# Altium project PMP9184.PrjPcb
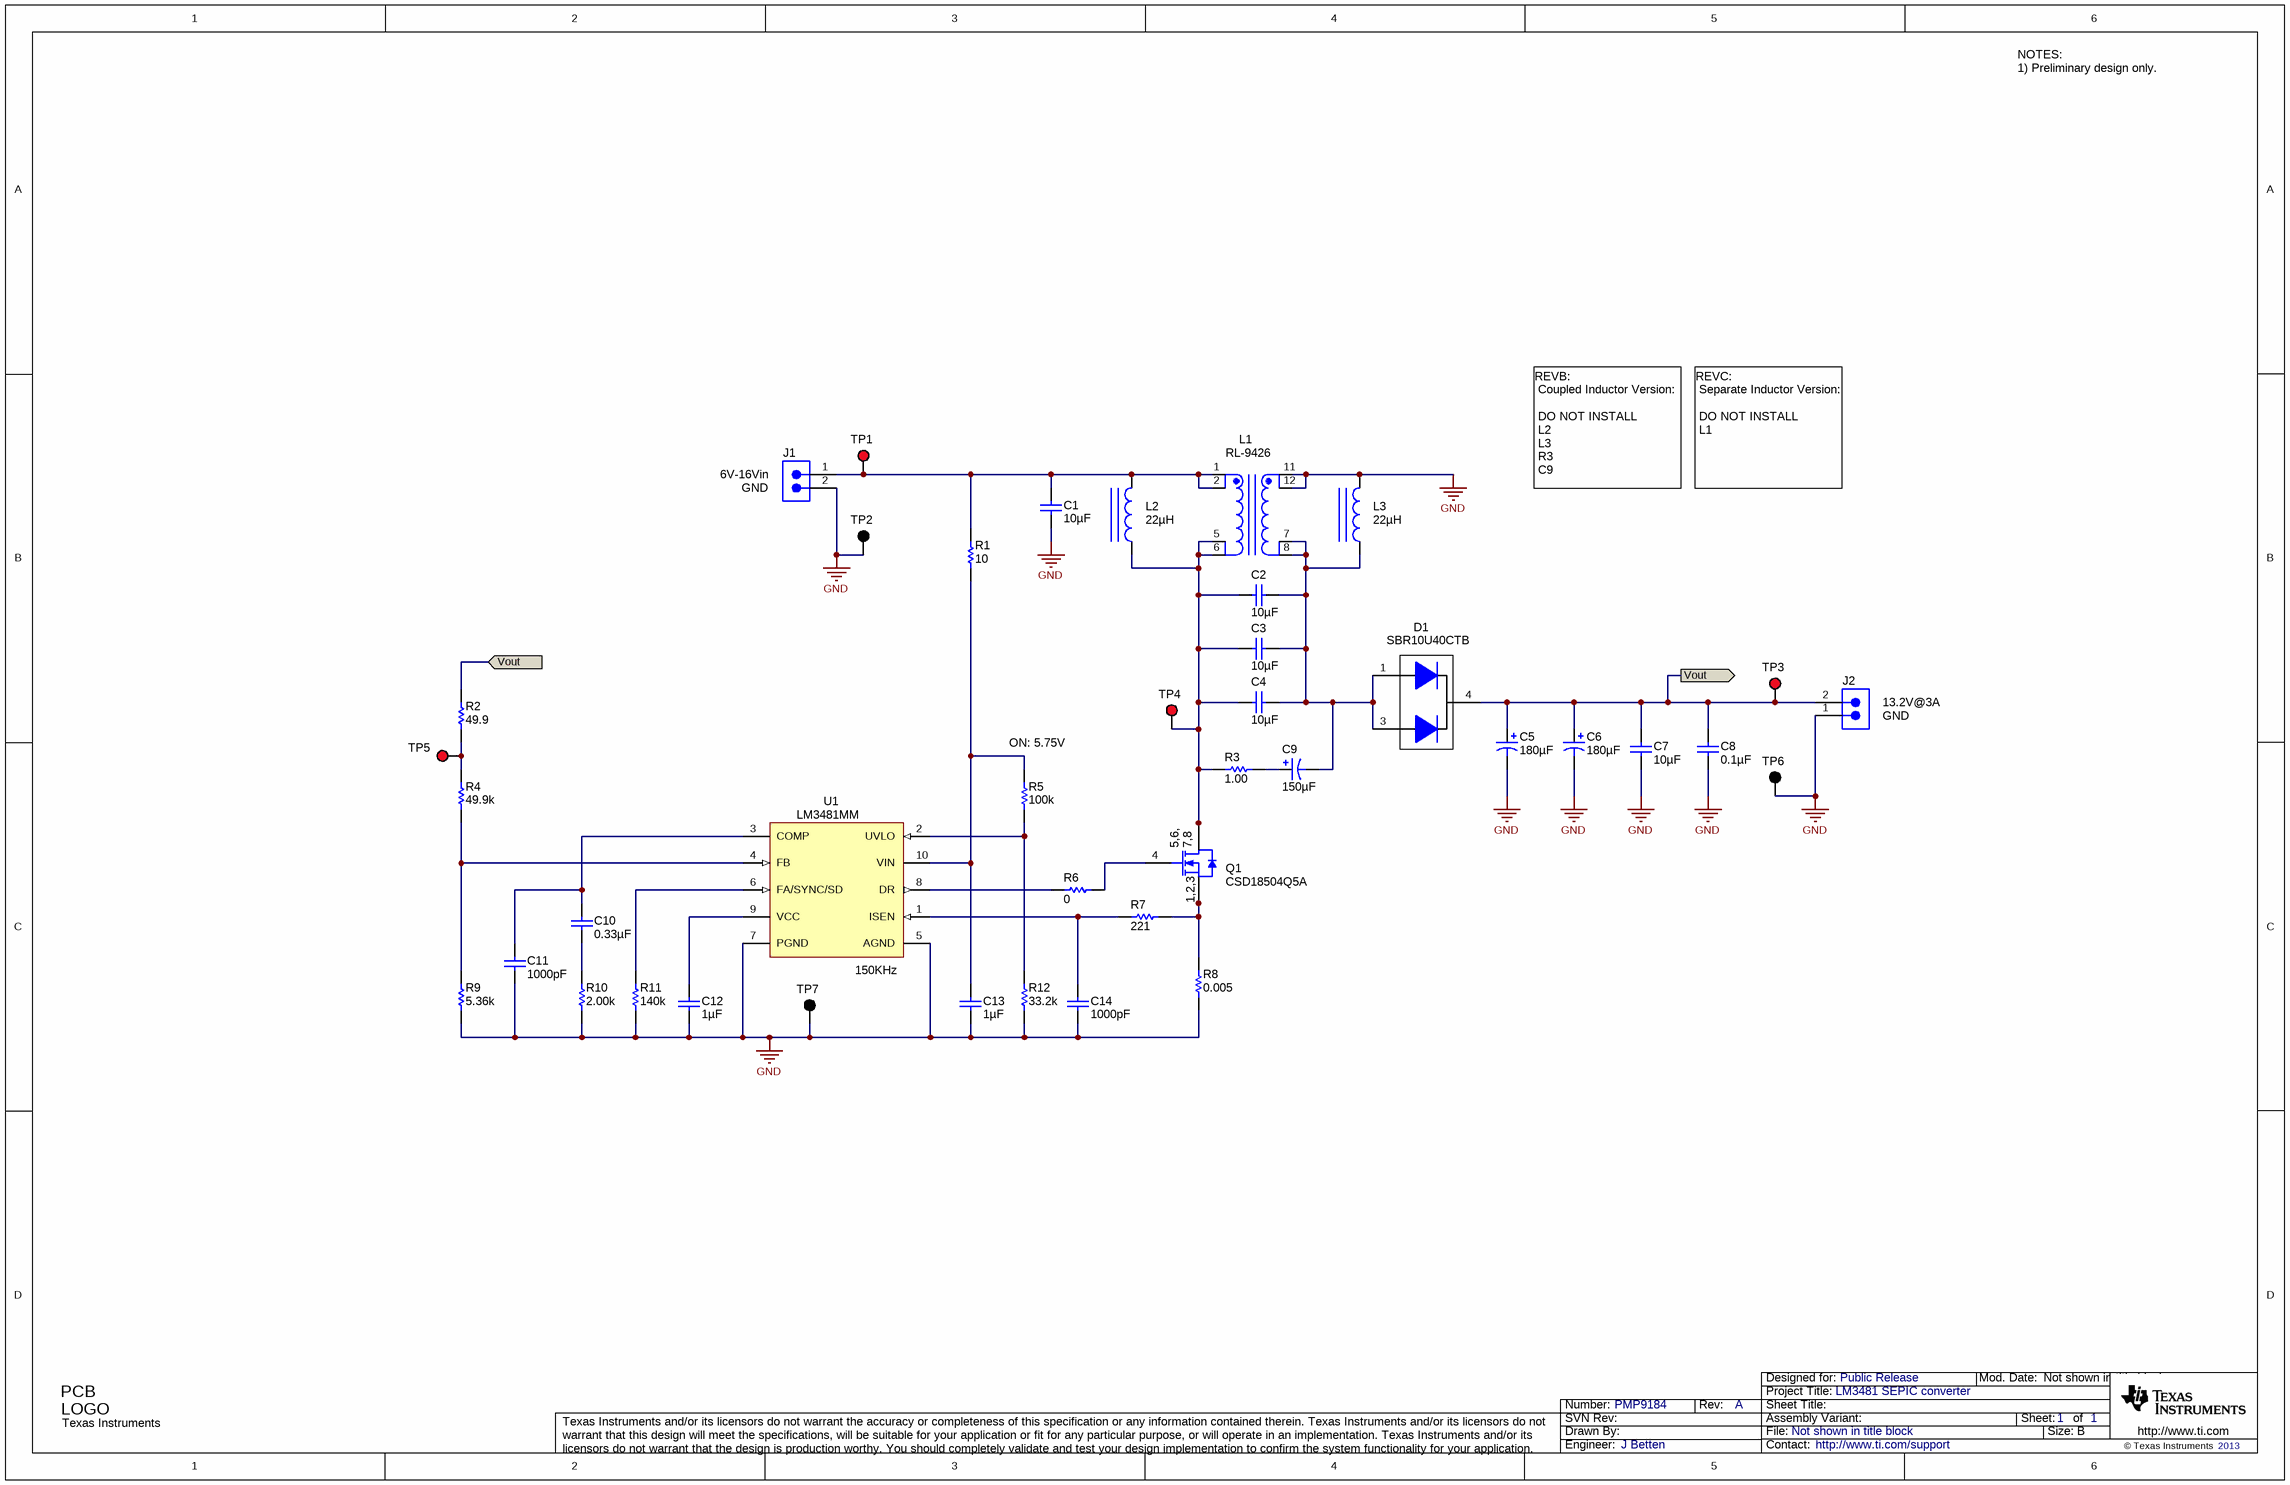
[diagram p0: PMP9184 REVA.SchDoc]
TechSupport: http://www.ti.com/support; SCH_Rev: A; PRJ_Title: LM3481 SEPIC converter; PRJ_Number: PMP9184; PRJ_Engineer: J Betten; PRJ_Customer: Public Release; PCB_Rev: A; PCB_Layout: J Betten; CopyrightYear: 2013
1 sheet, 42 parts. Net scope: flat (ports and power ports of the same name join across sheets).
Board file: PMP9184 REVA.PcbDoc

## Sheet PMP9184 REVA.SchDoc
size 431 x 279 mm; Date: Not shown in title block; ApprovedBy: Not shown in title block; CheckedBy: Not shown in title block; Author: Not shown in title block; CompanyName: Not shown in title block; Engineer: Not shown in title block; Organization: Not shown in title block; Address1: Not shown in title block; Address2: Not shown in title block; Address3: Not shown in title block; Address4: Not shown in title block; DocumentNumber: 1; Revision: Use project parameter SCH_Rev; SheetNumber: 1; SheetTotal: 1; PageSetup: Record=PageOptions|CenterHorizontal=True|CenterVertical=True|PrintScale=1.00|XCorrection=1.00|YCorrection=1.00|PrintKind=0|BorderSize=5000000|LeftOffset=0|BottomOffset=0|Orientation=2|PaperLength=1000|PaperWidth=1000|Scale=100|PaperSource=15|PrintQuality=600|MediaType=1|DitherType=10|PaperKind=Letter|PrintScaleMode=1

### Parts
C1  ValueDisplayed: 10µF  [1210L]  (hidden comment: C3225X7R1E106M250AC)
C2  ValueDisplayed: 10µF  [1210L]  (hidden comment: C3225X7R1E106M250AC)
C3  ValueDisplayed: 10µF  [1210L]  (hidden comment: C3225X7R1E106M250AC)
C4  ValueDisplayed: 10µF  [1210L]  (hidden comment: C3225X7R1E106M250AC)
C5  ValueDisplayed: 180µF  [SM_RADIAL_10AMM]  (hidden comment: 25SVPF180M)
C6  ValueDisplayed: 180µF  [SM_RADIAL_10AMM]  (hidden comment: 25SVPF180M)
C7  ValueDisplayed: 10µF  [1210L]  (hidden comment: C3225X7R1E106M250AC)
C8  ValueDisplayed: 0.1µF  [0603L]  (hidden comment: C1608X7R1H104K)
C9  ValueDisplayed: 150µF  [SM_RADIAL_F]  (hidden comment: EEE-FK1E151P)
C10  ValueDisplayed: 0.33µF  [0603L]  (hidden comment: C1608X5R1E474K)
C11  ValueDisplayed: 1000pF  [0603L]  (hidden comment: C1608X7R1H102K)
C12  ValueDisplayed: 1µF  [0603L]  (hidden comment: C1608X7R1E105K)
C13  ValueDisplayed: 1µF  [0603L]  (hidden comment: C1608X7R1E105K)
C14  ValueDisplayed: 1000pF  [0603L]  (hidden comment: C1608X7R1H102K)
D1  SBR10U40CTB  [DDPAK]
J1  ED555/2DS  [TERM_BLK_ED555-2DS]  (value not drawn)
J2  ED555/2DS  [TERM_BLK_ED555-2DS]  (value not drawn)
L1  RL-9426  [IND_RENCO_1050_X_1300]
L2  ValueDisplayed: 22µH  [IND_WE-HCI_2212]  (hidden comment: 74435582200)
L3  ValueDisplayed: 22µH  [WE-HCA2]  (hidden comment: 7443551221)
Logo1  Texas Instruments  [TI_Stacked_Overlay_Small]  (no BOM)
Q1  CSD18504Q5A  [TRANS_NexFET_Q5A]
R1  value 10  [0603L]  (hidden comment: CRCW060310R0JNEA)
R2  value 49.9  [0603L]  (hidden comment: CRCW060349R9FKEA)
R3  value 1.00  [1206L]  (hidden comment: CRCW12061R00FKEA)
R4  value 49.9k  [0603L]  (hidden comment: CRCW060349K9FKEA)
R5  value 100k  [0603L]  (hidden comment: CRCW0603100KFKEA)
R6  value 0  [0603L]  (hidden comment: CRCW06030000Z0EA)
R7  value 221  [0603L]  (hidden comment: CRCW0603221RFKEA)
R8  value 0.005  [2512L]  (hidden comment: CSNL2512FT5L00)
R9  value 5.36k  [0603L]  (hidden comment: CRCW06035K36FKEA)
R10  value 2.00k  [0603L]  (hidden comment: CRCW06032K00FKEA)
R11  value 140k  [0603L]  (hidden comment: CRCW0603140KFKEA)
R12  value 33.2k  [0603L]  (hidden comment: CRCW060333K2FKEA)
TP1  5000  [Keystone5000]  (value not drawn)
TP2  5001  [Keystone5001]  (value not drawn)
TP3  5000  [Keystone5000]  (value not drawn)
TP4  5000  [Keystone5000]  (value not drawn)
TP5  5000  [Keystone5000]  (value not drawn)
TP6  5001  [Keystone5001]  (value not drawn)
TP7  5001  [Keystone5001]  (value not drawn)
U1  LM3481MM  [MUB10A_L]

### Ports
Vout

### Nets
GND: C1.1 C5.2(-) C6.2(-) C7.1 C8.2 C11.2 C12.2 C13.2 C14.2 J1.2 J2.1 L1.11 L1.12 L3.2 R8.1 R9.1 R10.1 R11.1 R12.1 TP2.1 TP6.1 TP7.1 U1.5(AGND) U1.7(PGND)
Vout: C5.1(+) C6.1(+) C7.2 C8.1 D1.4(K) J2.2 R2.2 TP3.1 ; port Vout
NetC1_2: C1.2 J1.1 L1.1 L1.2 L2.2 R1.2 TP1.1
NetC2_1: C2.1 C3.1 C4.1 L1.5 L1.6 L2.1 Q1.5(D) Q1.6(D) Q1.7(D) Q1.8(D) Q1.9(D) R3.1 TP4.1
NetC2_2: C2.2 C3.2 C4.2 C9.2(-) D1.1(A) D1.3(A) L1.7 L1.8 L3.1
NetC9_1: C9.1(+) R3.2
NetC10_1: C10.1 C11.1 U1.3(COMP)
NetC10_2: C10.2 R10.2
NetC12_1: C12.1 U1.9(VCC)
NetC13_1: C13.1 R1.1 R5.2 U1.10(VIN)
NetC14_1: C14.1 R7.2 U1.1(ISEN)
NetQ1_1: Q1.1(S) Q1.2(S) Q1.3(S) R7.1 R8.2
NetQ1_4: Q1.4(G) R6.2
NetR2_1: R2.1 R4.2 TP5.1
NetR4_1: R4.1 R9.2 U1.4(FB)
NetR5_1: R5.1 R12.2 U1.2(UVLO)
NetR6_1: R6.1 U1.8(DR)
NetR11_2: R11.2 U1.6(FA/SYNC/SD)

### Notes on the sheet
- NOTES:
  1) Preliminary design only.
- (near J1) 6V-16Vin
- (near J1) GND
- REVB:
  Coupled Inductor Version:
  DO NOT INSTALL
  L2
  L3
  R3
  C9
- REVC:
  Separate Inductor Version:
  DO NOT INSTALL
  L1
- (near J2) 13.2V@3A
- (near R5) ON: 5.75V
- (near J2) GND
- (near U1) 150KHz

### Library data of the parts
C1-C4 C7 = C3225X7R1E106M: CAP, CERM, 10uF, 25V, +/-20%, X7R, 1210; Manufacturer: TDK; Polarized: N; CompType: Capacitor; U/M: EA; Cap_F: 0.00001; Tolerance_%: 20; ESR_Ohm: 0.0027; Value1: 0.0027 ohm; VDC_V: 25; IRMS_A: 3; TaMin_C: -55; TaMax_C: 125; Cap_Case: 1210
C5 C6 = 25SVP22M: CAP, OS-CON, 180uF, 25V, +/-20%, 0.016 ohm, 10x10.3 SMD; Manufacturer: Sanyo; Polarized: Y; CompType: Capacitor; U/M: EA; Cap_F: 0.000022; Tolerance_%: 20; VDC_V: 25; ESR_Ohm: 0.05; IRMS_A: 2; TaMin_C: -55; TaMax_C: 105; Cap_Case: 10.3x10.3x7.9
C8 = C1608X7R1H104K: CAP, CERM, 0.1uF, 50V, +/-10%, X7R, 0603; Manufacturer: TDK; Polarized: N; CompType: Capacitor; U/M: EA; Cap_F: 0.0000001; Tolerance_%: 10; ESR_Ohm: 0.017; Value1: 0.017 ohm; VDC_V: 50; TaMin_C: -55; TaMax_C: 125; Cap_Case: 0603
C9 = EEE-FK1E151P: CAP, AL, 150uF, 25V, +/-20%, 0.16 ohm, SMD; Manufacturer: Panasonic; Polarized: Y; CompType: Capacitor; U/M: EA; Cap_F: 0.00015; Tolerance_%: 20; VDC_V: 25; ESR_Ohm: 0.16; IRMS_A: 0.6; TaMin_C: -55; TaMax_C: 105; Cap_Case: F
C10 = C1608X5R1A474K: CAP, CERM, 0.33uF, 25V, +/-10%, X5R, 0603; Manufacturer: TDK; Polarized: N; CompType: Capacitor; U/M: EA; Cap_F: 0.00000047; Tolerance_%: 10; ESR_Ohm: 0.0101; Value1: 0.0101 ohm; VDC_V: 25; TaMin_C: -55; TaMax_C: 85; Cap_Case: 0603
C11 C14 = C1608X7R1H102K: CAP, CERM, 1000pF, 50V, +/-10%, X7R, 0603; Manufacturer: TDK; Polarized: N; CompType: Capacitor; U/M: EA; Cap_F: 0.000000001; Tolerance_%: 10; ESR_Ohm: 0.24; Value1: 0.24 ohm; VDC_V: 50; TaMin_C: -55; TaMax_C: 125; Cap_Case: 0603
C12 C13 = C1608X7R1C105K: CAP, CERM, 1uF, 25V, +/-10%, X7R, 0603; Manufacturer: TDK; Polarized: N; CompType: Capacitor; U/M: EA; Cap_F: 0.000001; Tolerance_%: 10; ESR_Ohm: 0.0057; Value1: 0.0057 ohm; VDC_V: 25; TaMin_C: -55; TaMax_C: 125; Cap_Case: 0603
D1 = SBR10U40CTB: Diode, Super Barrier Rectifier, 40V, 5A, DDPAK; Manufacturer: Diodes Inc.; RJC_CperW: 2; Vf_V: 0.47; Io_A: 5; Vr_V: 40; TJMax_C: 150; U/M: EA; Value2: 0.47V
J1 J2 = ED555/2DS: Terminal Block, 6A, 3.5mm Pitch, 2-Pos, TH; Manufacturer: On-Shore Technology, Inc.; SymbolCreator: a0412235; CompType: Connector; U/M: EA
L1 = IND_RL-9426: Inductor, Coupled, ±10%; Manufacturer: Renco; Area: 1490400; Value: 12 uH
L2 = 74435581000: Inductor, Drum Core, Ferrite, 22uH, 15A, 0.0070 ohm, SMD; Manufacturer: Wurth Elektronik eiSos; Value: 10uH; Ind_H: 10.0E-6; Imax_A: 21; Irms: 21A @ 50C rise; Isat: 26A @ 30% inductance drop; DCR_ohm: 0.0034; U/M: EA
L3 = 7443551181: Inductor, Shielded Drum Core, WE-Perm, 22uH, 6A, 0.0247 ohm, SMD; Manufacturer: Wurth Elektronik eiSos; Ind_H: 18.0E-6; Imax_A: 7.5; Irms: 7.5A @ 50C rise; Isat: 7.5A @ 30% inductance drop; DCR_ohm: 0.022; U/M: EA
Logo1 = TI_Logo: Texas Instrument Corporate Signature; SymbolCreator: codlsc
Q1 = CSD18504Q5A: MOSFET, N-CH, 40V, 15A, SON 5x6mm; Manufacturer: Texas Instruments; Alternate Manufacturer: None; U/M: EA; ChType: N; VdsMax_V: 40; Value1: 0.0098 ohm; Rdson45_Ohm: 0.0098; Value2: 7.7 nC; QgTyp_nC: 7.7; Vgs_V: 20; IdsMax_A: 15
R1 = CRCW060310R0JNEA: RES, 10 ohm, 1%, 0.1W, 0603; Manufacturer: Vishay-Dale; CompType: Resistor; Value_Code: 10R0; Tolerance_%: 5; Power_W: 0.1; VDC_V: 75; TempCo: 200 ppm/C; EIA_Code: E24; U/M: EA
R2 = CRCW060349R9FKEA: RES, 49.9 ohm, 1%, 0.1W, 0603; Manufacturer: Vishay-Dale; CompType: Resistor; Value_Code: 49R9; Tolerance_%: 1; Power_W: 0.1; VDC_V: 75; TempCo: 100 ppm/C; EIA_Code: E96; U/M: EA
R3 = CRCW12061R00FKEA: RES, 1.00 ohm, 1%, 0.25W, 1206; Manufacturer: Vishay-Dale; CompType: Resistor; Res_ohm: 1; Value_Code: 1R00; Power_W: 0.25; VDC_V: 200; TempCo: 100 ppm/C; EIA_Code: E96; U/M: EA
R4 = CRCW060349K9FKEA: RES, 49.9k ohm, 1%, 0.1W, 0603; Manufacturer: Vishay-Dale; CompType: Resistor; Res_ohm: 49900; Value_Code: 49k9; Tolerance_%: 1; Power_W: 0.1; VDC_V: 75; TempCo: 100 ppm/C; EIA_Code: E96; U/M: EA
R5 = CRCW0603100KFKEA: RES, 100k ohm, 1%, 0.1W, 0603; Manufacturer: Vishay-Dale; CompType: Resistor; Res_ohm: 100000; Tolerance_%: 1; Power_W: 0.1; VDC_V: 75; TempCo: 100 ppm/C; EIA_Code: E96; U/M: EA
R6 = CRCW06030000Z0EA: RES, 0 ohm, 5%, 0.1W, 0603; Manufacturer: Vishay-Dale; CompType: Resistor; Value_Code: 0000; Tolerance_%: 5; Power_W: 0.1; VDC_V: 75; TempCo: 200 ppm/C; EIA_Code: E24; U/M: EA
R7 = CRCW0603221RFKEA: RES, 221 ohm, 1%, 0.1W, 0603; Manufacturer: Vishay-Dale; CompType: Resistor; Value_Code: 221R; Tolerance_%: 1; Power_W: 0.1; VDC_V: 75; TempCo: 100 ppm/C; EIA_Code: E96; U/M: EA
R8 = CSNL2512FT5L00: RES, 0.005 ohm, 1%, 2W, 2512; Manufacturer: Stackpole Electronics Inc; CompType: Resistor; Value_Code: R005; Tolerance_%: 1; Power_W: 2; TempCo: 50 ppm/C; EIA_Code: E96; U/M: EA
R9 = CRCW06035K36FKEA: RES, 5.36k ohm, 1%, 0.1W, 0603; Manufacturer: Vishay-Dale; CompType: Resistor; Res_ohm: 5360; Value_Code: 5k36; Tolerance_%: 1; Power_W: 0.1; VDC_V: 75; TempCo: 100 ppm/C; EIA_Code: E96; U/M: EA
R10 = CRCW06032K00FKEA: RES, 2.00k ohm, 1%, 0.1W, 0603; Manufacturer: Vishay-Dale; CompType: Resistor; Res_ohm: 2000; Value_Code: 2k00; Tolerance_%: 1; Power_W: 0.1; VDC_V: 75; TempCo: 100 ppm/C; EIA_Code: E96; U/M: EA
R11 = CRCW0603140KFKEA: RES, 140k ohm, 1%, 0.1W, 0603; Manufacturer: Vishay-Dale; CompType: Resistor; Res_ohm: 140000; Tolerance_%: 1; Power_W: 0.1; VDC_V: 75; TempCo: 100 ppm/C; EIA_Code: E96; U/M: EA
R12 = CRCW060333K2FKEA: RES, 33.2k ohm, 1%, 0.1W, 0603; Manufacturer: Vishay-Dale; CompType: Resistor; Res_ohm: 33200; Value_Code: 33k2; Tolerance_%: 1; Power_W: 0.1; VDC_V: 75; TempCo: 100 ppm/C; EIA_Code: E96; U/M: EA
TP1 TP3-TP5 = 5000: Test Point, TH, Miniature, Red; Manufacturer: Keystone; CompType: Test Point Loop; U/M: EA
TP2 TP6 TP7 = 5001: Test Point, TH, Miniature, Black; Manufacturer: Keystone; CompType: Test Point Loop; U/M: EA
U1 = LM3481MM: High Efficiency Low-Side N-Channel Controller for Switching Regulators, 10-pin MSOP; Manufacturer: National Semiconductor; PackageTopMarking: ZXTT*SJPB; PowerWise: N; CompType: MiscPower

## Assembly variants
001: all parts fitted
